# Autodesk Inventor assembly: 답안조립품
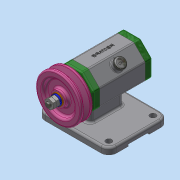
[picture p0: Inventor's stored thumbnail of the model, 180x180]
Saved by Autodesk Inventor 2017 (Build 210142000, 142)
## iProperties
Part Number: 답안조립품
Material: 일반
Document SubType Name: Assembly
Designer: MRC
Author: MRC
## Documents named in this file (16)
- C:\Users\MRC\Desktop\721006V1010\답안조립품.iam
- C:\Users\MRC\Desktop\721006V1010\본체.ipt
- C:\Users\MRC\Desktop\721006V1010\축.ipt
- C:\Users\MRC\Desktop\721006V1010\베어링 6002.ipt
- C:\Users\MRC\Desktop\721006V1010\앞커버.ipt
- C:\Users\MRC\Desktop\721006V1010\뒤커버.ipt
- C:\Users\MRC\Desktop\721006V1010\오일 실 15x25x7.ipt
- C:\Users\MRC\Desktop\721006V1010\볼트 M4x12.ipt
- C:\Users\MRC\Desktop\721006V1010\키 3x3x12.ipt
- 키 3x3x12.ipt
- C:\Users\MRC\Desktop\721006V1010\V벨트풀리.ipt
- C:\Users\MRC\Desktop\721006V1010\와셔 8x17.ipt
- C:\Users\MRC\Desktop\721006V1010\스프링와셔 8.ipt
- C:\Users\MRC\Desktop\721006V1010\너트 M8.ipt
- 너트 M8.ipt
- C:\Users\MRC\Desktop\721006V1010\고무캡.ipt
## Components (2 placed, 2 different names)
1. V벨트풀리:1
2. 고무캡:1
